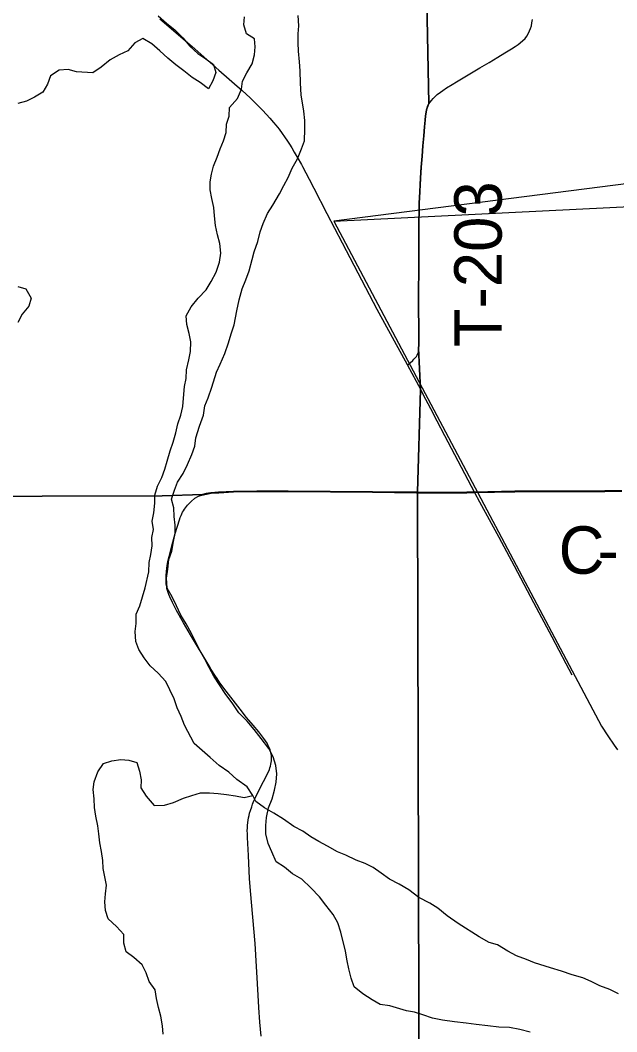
# Model space of a CAD drawing. Extents: x 0 to 34, y 0 to 22.
# Drawn here: x 4.548 to 5.262, y 16.855 to 18.065 of the extents above; entities that cross this region are included whole.
import ezdxf

# ---------------------------------------------------------------- set-up
doc = ezdxf.new("R2010")
doc.units = 0
for name, color, linetype in [('GM_X_Corporation', 7, 'Continuous'), ('GM_X_County_Road', 7, 'Continuous'), ('GM_X_County_Road_Text', 7, 'Continuous'), ('GM_X_Major_Lake', 7, 'Continuous'), ('GM_X_Minor_River', 7, 'Continuous'), ('GM_X_State_Route', 7, 'Continuous'), ('GM_X_Township_Road', 7, 'Continuous'), ('GM_X_Township_Road_Text', 7, 'Continuous'), ('SH_Data', 7, 'Continuous'), ('SH_Text', 7, 'Continuous')]:
    doc.layers.add(name, color=color, linetype=linetype)

msp = doc.modelspace()

# ---------------------------------------------------------------- linework, layer by layer
at = {"layer": 'GM_X_Corporation'}
for points in [[(3.7119, 17.4934), (4.718, 17.4962), (4.7665, 17.4977), (4.7708, 17.4988), (4.7764, 17.4996), (4.7857, 17.5004), (4.8033, 17.5014), (4.8313, 17.5017), (4.8462, 17.5018), (4.8689, 17.5017), (4.9697, 17.5009), (5.0115, 17.5005), (5.0235, 17.5004), (5.0273, 17.6235), (5.025, 17.6729), (5.0252, 17.6765), (5.0253, 17.6834), (5.0252, 17.6927), (5.0251, 17.7044), (5.025, 17.7135), (5.025, 17.7237), (5.025, 17.7332), (5.025, 17.7403), (5.025, 17.7488), (5.0251, 17.7581), (5.0251, 17.7673), (5.0252, 17.7738), (5.0252, 17.8099), (5.0254, 17.8228), (5.0256, 17.8382), (5.0258, 17.8465), (5.0264, 17.8598), (5.0269, 17.8687), (5.0273, 17.8763), (5.0277, 17.8835), (5.0281, 17.8893), (5.0291, 17.9025), (5.0301, 17.9148), (5.0311, 17.9269), (5.032, 17.9376), (5.0327, 17.9458), (5.0332, 17.9509), (5.0339, 17.9552), (5.0345, 17.9582), (5.0352, 17.9606), (5.0362, 17.9633), (5.0372, 17.9657), (5.0273, 18.4749)], [(3.7119, 17.4934), (4.718, 17.4962), (4.7665, 17.4977), (4.7708, 17.4988), (4.7764, 17.4996), (4.7857, 17.5004), (4.8033, 17.5014), (4.8313, 17.5017), (4.8462, 17.5018), (4.8689, 17.5017), (4.9697, 17.5009), (5.0224, 17.5004), (5.0235, 17.5004), (5.0273, 17.6235), (5.025, 17.6729), (5.0252, 17.6765), (5.0253, 17.6834), (5.0252, 17.6927), (5.0251, 17.7044), (5.025, 17.7135), (5.025, 17.7237), (5.025, 17.7332), (5.025, 17.7403), (5.025, 17.7488), (5.0251, 17.7581), (5.0251, 17.7673), (5.0252, 17.7738), (5.0252, 17.8099), (5.0254, 17.8228), (5.0256, 17.8382), (5.0258, 17.8465), (5.0264, 17.8598), (5.0269, 17.8687), (5.0273, 17.8763), (5.0277, 17.8835), (5.0281, 17.8893), (5.0291, 17.9025), (5.0301, 17.9148), (5.0311, 17.9269), (5.032, 17.9376), (5.0327, 17.9458), (5.0332, 17.9509), (5.0339, 17.9552), (5.0345, 17.9582), (5.0352, 17.9606), (5.0362, 17.9633), (5.0372, 17.9657), (5.0273, 18.4749)], [(5.0273, 18.4749), (5.0372, 17.9657), (5.0362, 17.9633), (5.0352, 17.9606), (5.0345, 17.9582), (5.0339, 17.9552), (5.0332, 17.9509), (5.0327, 17.9458), (5.032, 17.9376), (5.0311, 17.9269), (5.0301, 17.9148), (5.0291, 17.9025), (5.0281, 17.8893), (5.0277, 17.8835), (5.0273, 17.8763), (5.0269, 17.8687), (5.0264, 17.8598), (5.0258, 17.8465), (5.0256, 17.8382), (5.0254, 17.8228), (5.0252, 17.8099), (5.0252, 17.7738), (5.0251, 17.7673), (5.0251, 17.7581), (5.025, 17.7488), (5.025, 17.7403), (5.025, 17.7332), (5.025, 17.7237), (5.025, 17.7135), (5.0251, 17.7044), (5.0252, 17.6927), (5.0253, 17.6834), (5.0252, 17.6765), (5.025, 17.6729), (5.0273, 17.6235), (5.0235, 17.5004), (5.0547, 17.5001), (5.0827, 17.5003), (5.0918, 17.5004), (5.14, 17.5015), (5.203, 17.5018), (5.2477, 17.5019), (5.2682, 17.5021)], [(2.1, 14.1), (5.0398, 14.1), (5.0411, 14.425), (5.0381, 14.4922), (5.0378, 14.5635), (5.0395, 14.6051), (5.0366, 14.7668), (5.0353, 14.97), (5.0288, 16.3849), (5.0258, 16.7286), (5.0235, 17.4989), (5.0235, 17.5004), (5.0224, 17.5004), (4.9697, 17.5009), (4.8689, 17.5017), (4.8462, 17.5018), (4.8313, 17.5017), (4.8033, 17.5014), (4.7857, 17.5004), (4.7764, 17.4996), (4.7708, 17.4988), (4.7665, 17.4977), (4.718, 17.4962), (3.7119, 17.4934)], [(5.2682, 17.5021), (5.2477, 17.5019), (5.203, 17.5018), (5.14, 17.5015), (5.0918, 17.5004), (5.0827, 17.5003), (5.0547, 17.5001), (5.0235, 17.5004), (5.0235, 17.4989), (5.0258, 16.7286)]]:
    msp.add_lwpolyline(points, dxfattribs=at)
at = {"layer": 'GM_X_County_Road'}
for points in [[(4.8365, 16.8495), (4.835, 16.8662), (4.8338, 16.8836), (4.8331, 16.8985), (4.8296, 16.9604), (4.824, 17.0233), (4.8228, 17.0382), (4.8214, 17.0655), (4.8201, 17.0872), (4.8201, 17.0914), (4.82, 17.0954), (4.8202, 17.0984), (4.8203, 17.1016), (4.8207, 17.1051), (4.821, 17.1079), (4.8215, 17.1106), (4.8221, 17.1134), (4.8228, 17.1161), (4.8237, 17.1195), (4.8253, 17.1239), (4.8264, 17.1272), (4.828, 17.1309), (4.8293, 17.1341), (4.8342, 17.1442), (4.8444, 17.1641), (4.8464, 17.1686), (4.8471, 17.1707), (4.8477, 17.1726), (4.8482, 17.1747), (4.8486, 17.1768), (4.8488, 17.1789), (4.849, 17.181), (4.8489, 17.183), (4.8488, 17.1852), (4.8482, 17.1888), (4.8473, 17.1922), (4.8459, 17.1956), (4.8446, 17.198), (4.8436, 17.1999), (4.8416, 17.203), (4.8399, 17.2055), (4.8339, 17.2134), (4.8269, 17.2217), (4.8189, 17.2309), (4.8114, 17.2408), (4.7946, 17.2623), (4.7873, 17.2723), (4.7838, 17.2774), (4.7811, 17.2815), (4.7768, 17.2883), (4.7742, 17.2925), (4.7522, 17.3298), (4.7438, 17.3439), (4.7352, 17.359), (4.7303, 17.3684), (4.7272, 17.3752), (4.7262, 17.3779), (4.7252, 17.3804), (4.7246, 17.3829), (4.7239, 17.3853), (4.7236, 17.3874), (4.7231, 17.3903), (4.7229, 17.3931), (4.7228, 17.3953), (4.7228, 17.3981), (4.7229, 17.401), (4.7233, 17.405), (4.7237, 17.4093), (4.7241, 17.4121), (4.7245, 17.4149), (4.7255, 17.4189), (4.7265, 17.4234), (4.7298, 17.4361), (4.7338, 17.4511), (4.7387, 17.4672), (4.7398, 17.4701), (4.7407, 17.4725), (4.7417, 17.4746), (4.7426, 17.4765), (4.7437, 17.4783), (4.7449, 17.4803), (4.7485, 17.4848), (4.7527, 17.4893), (4.7573, 17.4933), (4.7617, 17.4955), (4.7668, 17.4972), (4.7676, 17.4974)], [(4.7676, 17.4974), (4.771, 17.4982), (4.7766, 17.4991), (4.7859, 17.4998), (4.8035, 17.5008), (4.8315, 17.5012), (4.8464, 17.5013), (4.8691, 17.5011), (4.9699, 17.5004), (5.0226, 17.4998), (5.0237, 17.4998)], [(5.0237, 17.4998), (5.0549, 17.4995), (5.0829, 17.4998), (5.092, 17.4999)], [(5.092, 17.4999), (5.1402, 17.5009), (5.2032, 17.5012), (5.2479, 17.5014), (5.2684, 17.5015)]]:
    msp.add_lwpolyline(points, dxfattribs=at)
at = {"layer": 'GM_X_Major_Lake'}
for points in [[(4.7134, 18.0704), (4.7233, 18.0617), (4.7332, 18.0538), (4.7428, 18.0444), (4.7512, 18.0343), (4.7607, 18.0256), (4.7702, 18.0192), (4.7797, 18.0125), (4.7825, 18.0026), (4.7787, 17.9927), (4.7735, 17.9832), (4.7636, 17.9907), (4.7541, 17.9967), (4.7442, 18.0046), (4.7343, 18.0121), (4.7248, 18.02), (4.7153, 18.0287), (4.7057, 18.0369), (4.6951, 18.0433), (4.6853, 18.0383), (4.677, 18.0287), (4.6665, 18.0241), (4.6559, 18.018), (4.645, 18.0092), (4.6352, 18.0023), (4.6155, 18.0036), (4.6057, 18.0062), (4.5947, 18.0054)], [(4.8082, 17.9715), (4.813, 17.9829), (4.8144, 17.9924), (4.8196, 18.0024), (4.8259, 18.0131), (4.8288, 18.0241), (4.8295, 18.0336), (4.8286, 18.0431), (4.8191, 18.0491), (4.8159, 18.06), (4.8166, 18.0695)], [(4.5947, 18.0054), (4.5846, 17.9988), (4.5808, 17.9889), (4.5752, 17.9794), (4.5654, 17.9733), (4.5556, 17.9683), (4.5455, 17.9655)], [(4.641, 17.1657), (4.6481, 17.1756), (4.6579, 17.1787), (4.6685, 17.1803), (4.6784, 17.1796), (4.6878, 17.1767), (4.691, 17.1665), (4.6929, 17.1562), (4.6926, 17.1464), (4.6991, 17.1366), (4.7087, 17.1256), (4.7208, 17.1257), (4.7317, 17.1289), (4.7438, 17.1343), (4.7536, 17.1374), (4.7642, 17.1405), (4.7748, 17.1406), (4.785, 17.1399), (4.7953, 17.1384), (4.8059, 17.137), (4.8161, 17.1352), (4.8267, 17.1372), (4.8198, 17.1477), (4.8076, 17.1567), (4.7981, 17.1654), (4.7863, 17.1733), (4.7756, 17.183), (4.7661, 17.1913), (4.7566, 17.1996), (4.745, 17.2215), (4.7408, 17.2321), (4.7362, 17.2423), (4.7323, 17.2529), (4.7273, 17.2638), (4.7227, 17.274), (4.7135, 17.2838), (4.7036, 17.2925), (4.6967, 17.3023), (4.6902, 17.3121), (4.6867, 17.3219), (4.6859, 17.3337), (4.6869, 17.3431), (4.6872, 17.3545), (4.6913, 17.3644), (4.6946, 17.3751), (4.6979, 17.3861), (4.7023, 17.4051), (4.7026, 17.4161), (4.7044, 17.4259), (4.7063, 17.4362), (4.7058, 17.4461), (4.7076, 17.4556), (4.706, 17.4658), (4.7082, 17.4757), (4.7093, 17.4874), (4.7092, 17.4969), (4.7125, 17.5075), (4.7177, 17.5182), (4.7214, 17.5281), (4.724, 17.5376), (4.7277, 17.5498), (4.7314, 17.5604), (4.7343, 17.5714), (4.7369, 17.5824), (4.7406, 17.5927), (4.7428, 17.603), (4.7435, 17.6128), (4.7449, 17.6269), (4.7467, 17.6364), (4.7474, 17.647), (4.7499, 17.6588), (4.7521, 17.669), (4.7524, 17.6804), (4.7504, 17.6903), (4.7477, 17.7012), (4.7469, 17.7115), (4.7528, 17.7221), (4.7611, 17.7328), (4.7709, 17.7428), (4.7768, 17.7527), (4.7828, 17.7637), (4.7869, 17.7759), (4.7883, 17.7865), (4.7871, 17.7979), (4.7843, 17.8085), (4.782, 17.8198), (4.7808, 17.8312), (4.7799, 17.841), (4.7776, 17.852), (4.7756, 17.8623), (4.7755, 17.8717), (4.777, 17.8812), (4.7795, 17.8907), (4.784, 17.9014), (4.7877, 17.9113), (4.7914, 17.9208), (4.7947, 17.931), (4.795, 17.9409), (4.7984, 17.9504), (4.7987, 17.961), (4.8082, 17.9715)], [(4.5453, 17.7467), (4.5551, 17.7437), (4.5613, 17.7328), (4.5587, 17.7229), (4.5504, 17.7134), (4.5452, 17.7035)], [(4.7195, 16.8519), (4.7187, 16.8618), (4.7167, 16.8731), (4.7136, 16.8837), (4.7113, 16.8943), (4.7097, 16.9049), (4.7024, 16.9147), (4.6989, 16.925), (4.6943, 16.9348), (4.6844, 16.9434), (4.6749, 16.9502), (4.6721, 16.9608), (4.6721, 16.971), (4.6633, 16.9808), (4.6534, 16.9898), (4.6503, 16.9997), (4.6494, 17.0103), (4.6505, 17.0198), (4.6515, 17.03), (4.6496, 17.0402), (4.6476, 17.0501), (4.6471, 17.0596), (4.6455, 17.0705), (4.6436, 17.0808), (4.6423, 17.0914), (4.6411, 17.1012), (4.6388, 17.1126), (4.6372, 17.1232), (4.6367, 17.1334), (4.6355, 17.1444), (4.6366, 17.1539), (4.641, 17.1657)]]:
    msp.add_lwpolyline(points, dxfattribs=at)
at = {"layer": 'GM_X_Minor_River'}
for points in [[(4.7798, 17.2801), (4.7744, 17.2907), (4.769, 17.3005), (4.7632, 17.3111), (4.7586, 17.3209), (4.7533, 17.3311), (4.7467, 17.3428), (4.7406, 17.3534), (4.7352, 17.3644), (4.7302, 17.3753), (4.7241, 17.3855), (4.7232, 17.3977), (4.725, 17.4083), (4.7261, 17.42), (4.7298, 17.4299), (4.7316, 17.4413), (4.7338, 17.4508), (4.7337, 17.4611), (4.7325, 17.4713), (4.732, 17.4819), (4.7293, 17.4921), (4.733, 17.5028), (4.7363, 17.5123), (4.7431, 17.5226), (4.7486, 17.5336), (4.7535, 17.5454), (4.7572, 17.5557), (4.7586, 17.5655), (4.763, 17.5796), (4.7675, 17.5925), (4.7693, 17.6036), (4.773, 17.6134), (4.7774, 17.626), (4.783, 17.6442), (4.7874, 17.6538), (4.793, 17.6663), (4.7975, 17.6792), (4.8008, 17.6899), (4.8041, 17.7009), (4.8074, 17.7176), (4.8103, 17.7305), (4.814, 17.7438), (4.8184, 17.7545), (4.8221, 17.7655), (4.8258, 17.7788), (4.8284, 17.7883), (4.8328, 17.8005), (4.8354, 17.8119), (4.8391, 17.8222), (4.8443, 17.834), (4.8507, 17.8439), (4.8585, 17.8576), (4.8637, 17.8675), (4.869, 17.877), (4.8738, 17.8884), (4.8801, 17.8995), (4.885, 17.9113), (4.8883, 17.9208), (4.8889, 17.9348), (4.8889, 17.9454), (4.8876, 17.9564), (4.8845, 17.9761), (4.8836, 17.9901), (4.8831, 18.0046), (4.8823, 18.0155), (4.8814, 18.0281), (4.881, 18.0383), (4.8809, 18.0489), (4.8816, 18.0588), (4.8807, 18.0709)], [(5.1585, 16.8542), (5.146, 16.8575), (5.1339, 16.8597), (5.121, 16.86), (5.1078, 16.8618), (5.0938, 16.8632), (5.082, 16.865), (5.068, 16.8664), (5.0536, 16.8685), (5.0418, 16.8707), (5.0301, 16.8748), (5.0202, 16.8781), (5.0104, 16.8796), (4.9906, 16.8855), (4.9789, 16.8873), (4.9694, 16.8929), (4.9584, 16.9), (4.9481, 16.9083), (4.9442, 16.9189), (4.9415, 16.9299), (4.9395, 16.9397), (4.9375, 16.9511), (4.932, 16.9738), (4.9282, 16.9848), (4.9228, 16.9949), (4.914, 17.0063), (4.9063, 17.0161), (4.896, 17.027), (4.8854, 17.0371), (4.874, 17.0435), (4.8644, 17.0518), (4.8545, 17.0581), (4.8492, 17.0698), (4.8449, 17.08), (4.8422, 17.0914), (4.8421, 17.1016), (4.8428, 17.1111), (4.8453, 17.1225), (4.8498, 17.1336), (4.8527, 17.1438), (4.8546, 17.1533), (4.8552, 17.1632), (4.854, 17.1734), (4.8509, 17.1836), (4.8459, 17.1938), (4.8367, 17.2055), (4.8283, 17.2164), (4.8199, 17.2262), (4.81, 17.2364), (4.8027, 17.2473), (4.7936, 17.2594), (4.7867, 17.27), (4.7798, 17.2801)], [(5.2642, 16.9001), (5.2539, 16.905), (5.2418, 16.9094), (5.2315, 16.9147), (5.2216, 16.9191), (5.2087, 16.9228), (5.1962, 16.9273), (5.1829, 16.931), (5.1636, 16.9373), (5.1541, 16.941), (5.1423, 16.9454), (5.132, 16.9511), (5.1195, 16.9585), (5.1093, 16.9615), (5.0975, 16.9682), (5.0724, 16.984), (5.0594, 16.9933), (5.048, 17.0027), (5.0385, 17.0087), (5.0252, 17.0155), (5.0134, 17.0245), (5.0016, 17.0312), (4.9902, 17.0372), (4.9803, 17.0443), (4.9708, 17.0511), (4.9609, 17.0559), (4.9503, 17.06), (4.9381, 17.066), (4.9279, 17.0701), (4.9161, 17.0768), (4.9055, 17.0824), (4.8959, 17.088), (4.8864, 17.0948), (4.8758, 17.1004), (4.8632, 17.109), (4.8518, 17.1161), (4.8404, 17.1225), (4.8301, 17.1304), (4.8267, 17.1372)]]:
    msp.add_lwpolyline(points, dxfattribs=at)
at = {"layer": 'GM_X_State_Route'}
for points in [[(4.7153, 18.067), (4.754, 18.0338), (4.7861, 18.0054), (4.8137, 17.9812), (4.8233, 17.9723), (4.8279, 17.9679), (4.8336, 17.9623), (4.8381, 17.9576), (4.843, 17.9524), (4.847, 17.948), (4.8513, 17.943), (4.854, 17.9397), (4.858, 17.9348), (4.8617, 17.9298), (4.8647, 17.9258), (4.8681, 17.9206), (4.8706, 17.917), (4.8734, 17.9124), (4.8762, 17.9076), (4.8798, 17.9015), (4.885, 17.8926), (4.8862, 17.8903), (4.894, 17.875), (4.8995, 17.8643)], [(4.8995, 17.8643), (4.915, 17.8341), (4.9337, 17.7989), (4.9614, 17.7455), (4.975, 17.7196), (4.9956, 17.6817), (5.0113, 17.6533)], [(5.0113, 17.6533), (5.0118, 17.6524), (5.0221, 17.6332), (5.0275, 17.623)], [(5.0275, 17.623), (5.0302, 17.6178), (5.0392, 17.6007), (5.0469, 17.5858), (5.0561, 17.5682), (5.0719, 17.5379), (5.0878, 17.5077), (5.092, 17.4999)], [(5.092, 17.4999), (5.0978, 17.489), (5.1209, 17.4466), (5.1393, 17.4121), (5.1625, 17.3685), (5.1844, 17.3273), (5.2013, 17.2952), (5.2082, 17.2817)]]:
    msp.add_lwpolyline(points, dxfattribs=at)
at = {"layer": 'GM_X_Township_Road'}
for points in [[(5.0374, 17.9651), (5.039, 17.9674), (5.0405, 17.9694), (5.0426, 17.9717), (5.0447, 17.9739), (5.0474, 17.9763), (5.0511, 17.9791), (5.0542, 17.9814), (5.0585, 17.9843), (5.0653, 17.9885), (5.0702, 17.9916), (5.0863, 18.001), (5.0984, 18.0082), (5.1093, 18.0147), (5.12, 18.0211), (5.1282, 18.0261), (5.1361, 18.0309), (5.1405, 18.0338), (5.1441, 18.0363), (5.1495, 18.0406), (5.1524, 18.0434), (5.1545, 18.0462), (5.1562, 18.0489), (5.1579, 18.0525), (5.1591, 18.0554), (5.16, 18.0586), (5.1607, 18.0621), (5.1612, 18.0661)], [(5.0252, 17.6723), (5.0254, 17.6759), (5.0255, 17.6828), (5.0254, 17.6921), (5.0253, 17.7039), (5.0253, 17.713), (5.0252, 17.7231), (5.0252, 17.7326), (5.0252, 17.7397), (5.0252, 17.7483), (5.0253, 17.7576), (5.0253, 17.7667), (5.0254, 17.7732), (5.0254, 17.8094), (5.0256, 17.8222), (5.0258, 17.8376), (5.026, 17.846), (5.0266, 17.8593), (5.0271, 17.8681), (5.0275, 17.8757), (5.0279, 17.8829), (5.0283, 17.8887), (5.0293, 17.902), (5.0303, 17.9142), (5.0313, 17.9263), (5.0322, 17.9371), (5.0329, 17.9452), (5.0334, 17.9503), (5.0341, 17.9547), (5.0347, 17.9576), (5.0354, 17.9601), (5.0364, 17.9627), (5.0374, 17.9651)], [(5.0118, 17.6524), (5.0182, 17.6581), (5.0195, 17.6595), (5.0213, 17.6616), (5.0224, 17.6629), (5.0234, 17.6646), (5.0241, 17.6665), (5.0247, 17.6682), (5.0249, 17.67), (5.0251, 17.6712), (5.0252, 17.6723)]]:
    msp.add_lwpolyline(points, dxfattribs=at)
at = {"layer": 'SH_Data'}
msp.add_lwpolyline([(4.9237, 17.8249), (5.2441, 17.2203), (5.2514, 17.2089), (5.259, 17.1975), (5.2632, 17.1919)], dxfattribs=at)
at = {"layer": 'SH_Text'}
msp.add_lwpolyline([(9.3865, 18.3957), (4.9237, 17.8249), (9.3865, 18.0457)], close=True, dxfattribs=at)

# ---------------------------------------------------------------- texts
at = {"layer": 'GM_X_County_Road_Text'}
for s, rotation, p in [('C', 0, (5.1926, 17.4028)), ('-', 0.0117, (5.2392, 17.4028))]:
    msp.add_text(s, height=0.0568, rotation=rotation, dxfattribs=at).set_placement(p)
at = {"layer": 'GM_X_Township_Road_Text'}
msp.add_text('T-203', height=0.05682, rotation=90, dxfattribs=at).set_placement((5.1245, 17.674))

doc.saveas('drawing.dxf')
